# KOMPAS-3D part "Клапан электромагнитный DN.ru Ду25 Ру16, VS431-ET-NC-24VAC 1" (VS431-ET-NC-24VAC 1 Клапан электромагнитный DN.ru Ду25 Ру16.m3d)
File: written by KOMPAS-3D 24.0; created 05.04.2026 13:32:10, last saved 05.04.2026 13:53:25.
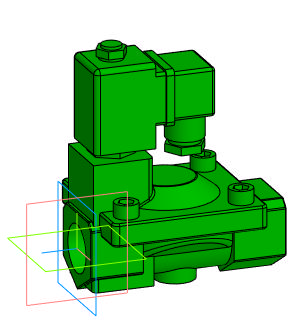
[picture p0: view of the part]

Document properties: Автор: artio; Полное имя файла: C:\Users\artio\OneDrive\Рабочий стол\Клапан электромагнитный DN.ru\VS431\VS431-ET-NC\VS431-ET-NC-24VAC\Ду25\VS431-ET-NC-24VAC 1 Клапан электромагнитный DN.ru Ду25 Ру16.m3d

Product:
- Body: Тело 1  | qty 1
    Масса: 1.729172
- Part/product: Клапан электромагнитный DN.ru Ду25 Ру16  | designation VS431-ET-NC-24VAC 1
    Масса: 1.267
    Раздел спецификации: Прочие изделия
    Примечание: D130-05504
    additional columns: ef56311e-7521-43dc-8291-0e6108b3d81d; artio; c; Шероховатость не задана; Да

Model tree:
1. Операция без истории:1

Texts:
  VS431-ET-NC-24VAC 1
